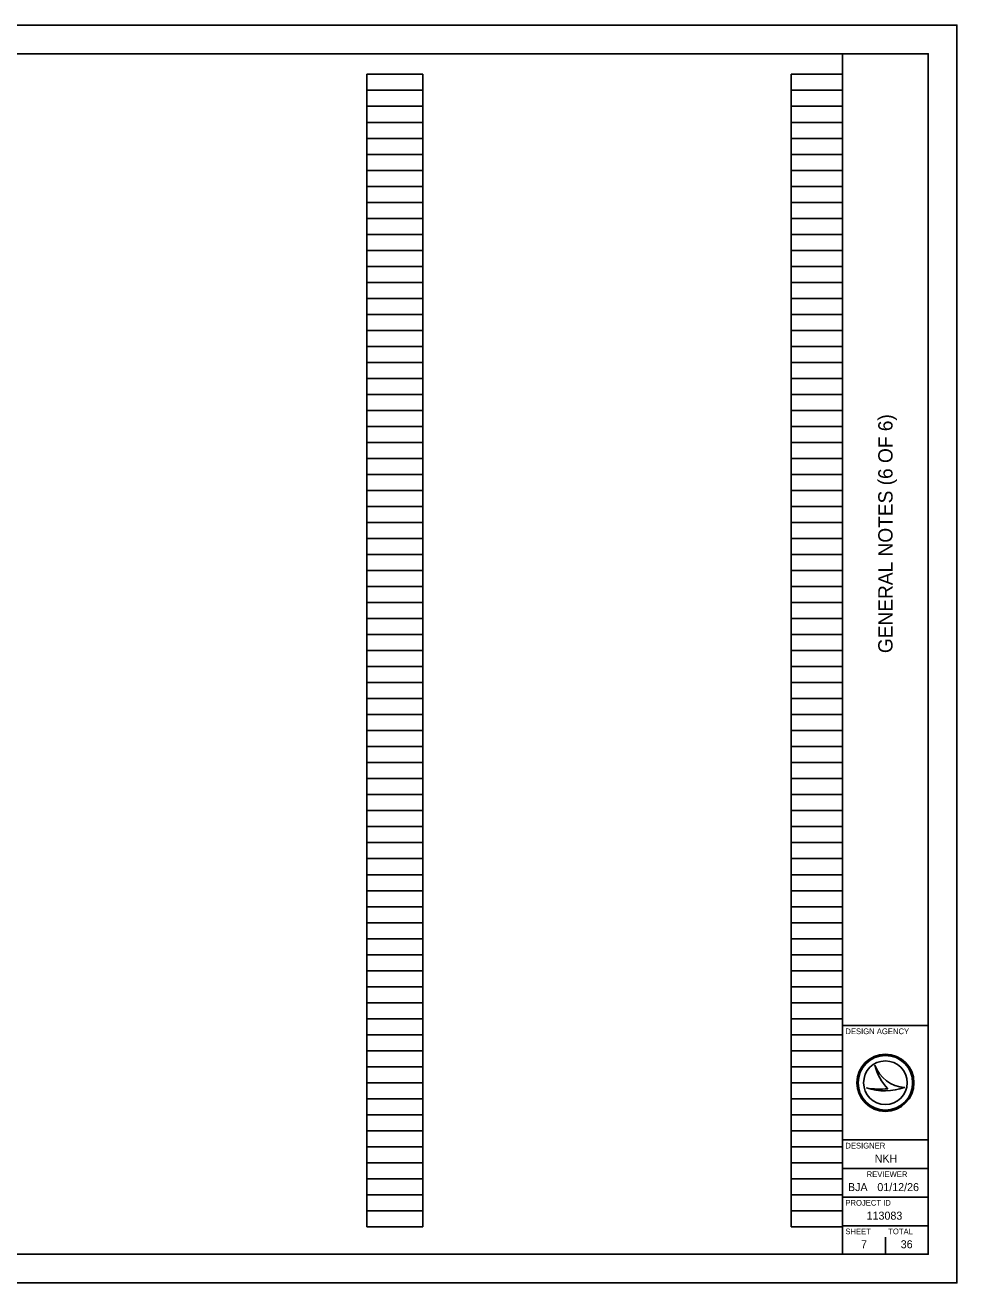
# Model space of a CAD drawing. Extents: x -26.8 to 34, y 0 to 22.
# Drawn here: x 17.7 to 34, y 0 to 22 of the extents above; entities that cross this region are included whole.
import ezdxf

# ---------------------------------------------------------------- set-up
doc = ezdxf.new("R2010")
doc.units = 0
for name, color, linetype in [('SH_Border', 7, 'Continuous'), ('SH_Cut_Line', 7, 'Continuous'), ('SH_Data', 7, 'Continuous')]:
    doc.layers.add(name, color=color, linetype=linetype)

msp = doc.modelspace()

# ---------------------------------------------------------------- linework, layer by layer
at = {"layer": 'SH_Border'}
for p, q in [((32, 0.5), (32, 21.5)), ((32, 4.5), (33.5, 4.5)), ((32, 2.5), (33.5, 2.5)), ((32, 2), (33.5, 2)), ((32, 1.5), (33.5, 1.5)), ((32, 1), (33.5, 1))]:
    msp.add_line(p, q, dxfattribs=at)
msp.add_lwpolyline([(1.5, 21.5), (33.5, 21.5), (33.5, 0.5), (1.5, 0.5)], close=True, dxfattribs=at)
at = {"layer": 'SH_Cut_Line'}
msp.add_lwpolyline([(0, 0), (34, 0), (34, 22), (0, 22)], close=True, dxfattribs=at)
at = {"layer": 'SH_Data'}
for p, q in [((23.68, 0.98), (23.68, 21.14)), ((23.68, 21.14), (24.66, 21.14)), ((24.66, 0.98), (24.66, 21.14)), ((31.1, 0.98), (31.1, 21.14)), ((31.1, 21.14), (32, 21.14)), ((32, 0.98), (32, 21.14)), ((23.68, 20.86), (24.66, 20.86)), ((31.1, 20.86), (32, 20.86)), ((23.68, 20.58), (24.66, 20.58)), ((31.1, 20.58), (32, 20.58)), ((23.68, 20.3), (24.66, 20.3)), ((31.1, 20.3), (32, 20.3)), ((23.68, 20.02), (24.66, 20.02)), ((31.1, 20.02), (32, 20.02)), ((23.68, 19.74), (24.66, 19.74)), ((31.1, 19.74), (32, 19.74)), ((23.68, 19.46), (24.66, 19.46)), ((31.1, 19.46), (32, 19.46)), ((23.68, 19.18), (24.66, 19.18)), ((31.1, 19.18), (32, 19.18)), ((23.68, 18.9), (24.66, 18.9)), ((31.1, 18.9), (32, 18.9)), ((23.68, 18.62), (24.66, 18.62)), ((31.1, 18.62), (32, 18.62)), ((23.68, 18.34), (24.66, 18.34)), ((31.1, 18.34), (32, 18.34)), ((23.68, 18.06), (24.66, 18.06)), ((31.1, 18.06), (32, 18.06)), ((23.68, 17.78), (24.66, 17.78)), ((31.1, 17.78), (32, 17.78)), ((23.68, 17.5), (24.66, 17.5)), ((31.1, 17.5), (32, 17.5)), ((23.68, 17.22), (24.66, 17.22)), ((31.1, 17.22), (32, 17.22)), ((23.68, 16.94), (24.66, 16.94)), ((31.1, 16.94), (32, 16.94)), ((23.68, 16.66), (24.66, 16.66)), ((31.1, 16.66), (32, 16.66)), ((23.68, 16.38), (24.66, 16.38)), ((31.1, 16.38), (32, 16.38)), ((23.68, 16.1), (24.66, 16.1)), ((31.1, 16.1), (32, 16.1)), ((23.68, 15.82), (24.66, 15.82)), ((31.1, 15.82), (32, 15.82)), ((23.68, 15.54), (24.66, 15.54)), ((31.1, 15.54), (32, 15.54)), ((23.68, 15.26), (24.66, 15.26)), ((31.1, 15.26), (32, 15.26)), ((23.68, 14.98), (24.66, 14.98)), ((31.1, 14.98), (32, 14.98)), ((23.68, 14.7), (24.66, 14.7)), ((31.1, 14.7), (32, 14.7)), ((23.68, 14.42), (24.66, 14.42)), ((31.1, 14.42), (32, 14.42)), ((23.68, 14.14), (24.66, 14.14)), ((31.1, 14.14), (32, 14.14)), ((23.68, 13.86), (24.66, 13.86)), ((31.1, 13.86), (32, 13.86)), ((23.68, 13.58), (24.66, 13.58)), ((31.1, 13.58), (32, 13.58)), ((23.68, 13.3), (24.66, 13.3)), ((31.1, 13.3), (32, 13.3)), ((23.68, 13.02), (24.66, 13.02)), ((31.1, 13.02), (32, 13.02)), ((23.68, 12.74), (24.66, 12.74)), ((31.1, 12.74), (32, 12.74)), ((23.68, 12.46), (24.66, 12.46)), ((31.1, 12.46), (32, 12.46)), ((23.68, 12.18), (24.66, 12.18)), ((31.1, 12.18), (32, 12.18)), ((23.68, 11.9), (24.66, 11.9)), ((31.1, 11.9), (32, 11.9)), ((23.68, 11.62), (24.66, 11.62)), ((31.1, 11.62), (32, 11.62)), ((23.68, 11.34), (24.66, 11.34)), ((31.1, 11.34), (32, 11.34)), ((23.68, 11.06), (24.66, 11.06)), ((31.1, 11.06), (32, 11.06)), ((23.68, 10.78), (24.66, 10.78)), ((31.1, 10.78), (32, 10.78)), ((23.68, 10.5), (24.66, 10.5)), ((31.1, 10.5), (32, 10.5)), ((23.68, 10.22), (24.66, 10.22)), ((31.1, 10.22), (32, 10.22)), ((23.68, 9.94), (24.66, 9.94)), ((31.1, 9.94), (32, 9.94)), ((23.68, 9.66), (24.66, 9.66)), ((31.1, 9.66), (32, 9.66)), ((23.68, 9.38), (24.66, 9.38)), ((31.1, 9.38), (32, 9.38)), ((23.68, 9.1), (24.66, 9.1)), ((31.1, 9.1), (32, 9.1)), ((23.68, 8.82), (24.66, 8.82)), ((31.1, 8.82), (32, 8.82)), ((23.68, 8.54), (24.66, 8.54)), ((31.1, 8.54), (32, 8.54)), ((23.68, 8.26), (24.66, 8.26)), ((31.1, 8.26), (32, 8.26)), ((23.68, 7.98), (24.66, 7.98)), ((31.1, 7.98), (32, 7.98)), ((23.68, 7.7), (24.66, 7.7)), ((31.1, 7.7), (32, 7.7)), ((23.68, 7.42), (24.66, 7.42)), ((31.1, 7.42), (32, 7.42)), ((23.68, 7.14), (24.66, 7.14)), ((31.1, 7.14), (32, 7.14)), ((23.68, 6.86), (24.66, 6.86)), ((31.1, 6.86), (32, 6.86)), ((23.68, 6.58), (24.66, 6.58)), ((31.1, 6.58), (32, 6.58)), ((23.68, 6.3), (24.66, 6.3)), ((31.1, 6.3), (32, 6.3)), ((23.68, 6.02), (24.66, 6.02)), ((31.1, 6.02), (32, 6.02)), ((23.68, 5.74), (24.66, 5.74)), ((31.1, 5.74), (32, 5.74)), ((23.68, 5.46), (24.66, 5.46)), ((31.1, 5.46), (32, 5.46)), ((23.68, 5.18), (24.66, 5.18)), ((31.1, 5.18), (32, 5.18)), ((23.68, 4.9), (24.66, 4.9)), ((31.1, 4.9), (32, 4.9)), ((23.68, 4.62), (24.66, 4.62)), ((31.1, 4.62), (32, 4.62)), ((23.68, 4.34), (24.66, 4.34)), ((31.1, 4.34), (32, 4.34)), ((23.68, 4.06), (24.66, 4.06)), ((31.1, 4.06), (32, 4.06)), ((23.68, 3.78), (24.66, 3.78)), ((31.1, 3.78), (32, 3.78)), ((32.567, 3.81), (32.567, 3.81)), ((23.68, 3.5), (24.66, 3.5)), ((31.1, 3.5), (32, 3.5)), ((32.417, 3.41), (32.417, 3.41)), ((32.75, 3.5), (32.75, 3.5)), ((33.087, 3.419), (33.087, 3.419)), ((23.68, 3.22), (24.66, 3.22)), ((31.1, 3.22), (32, 3.22)), ((23.68, 2.94), (24.66, 2.94)), ((31.1, 2.94), (32, 2.94)), ((23.68, 2.66), (24.66, 2.66)), ((31.1, 2.66), (32, 2.66)), ((23.68, 2.38), (24.66, 2.38)), ((31.1, 2.38), (32, 2.38)), ((23.68, 2.1), (24.66, 2.1)), ((31.1, 2.1), (32, 2.1)), ((23.68, 1.82), (24.66, 1.82)), ((31.1, 1.82), (32, 1.82)), ((23.68, 1.54), (24.66, 1.54)), ((31.1, 1.54), (32, 1.54)), ((23.68, 1.26), (24.66, 1.26)), ((31.1, 1.26), (32, 1.26)), ((23.68, 0.98), (24.66, 0.98)), ((31.1, 0.98), (32, 0.98)), ((32.375, 0.675), (32.375, 0.675)), ((32.75, 0.5), (32.75, 0.8))]:
    msp.add_line(p, q, dxfattribs=at)
for radius in [0.5, 0.477, 0.477, 0.382]:
    msp.add_circle((32.75, 3.5), radius, dxfattribs=at)
for centre, radius, start, end in [((33.116, 3.998), 0.58, 198.9257, 198.9319), ((33.347, 3.97), 0.796, 191.6379, 191.6421), ((33.116, 3.998), 0.58, 198.9319, 267.1657), ((33.347, 3.97), 0.796, 191.6421, 226.0947), ((32.739, 4.37), 1.013, 251.4576, 290.0832), ((32.648, 4.654), 1.266, 259.4964, 259.4995), ((32.739, 4.37), 1.013, 251.4527, 251.4576), ((32.648, 4.654), 1.266, 259.4995, 276.6672)]:
    msp.add_arc(centre, radius, start, end, dxfattribs=at)

# ---------------------------------------------------------------- texts
msp.add_text('GENERAL NOTES (6 OF 6)', height=0.25, rotation=90, dxfattribs=at).set_placement((32.875, 11.015))
for s, height, p in [('DESIGN AGENCY', 0.1, (32.05, 4.35)), ('DESIGNER', 0.1, (32.05, 2.35)), ('NKH', 0.14, (32.562, 2.105)), ('REVIEWER', 0.1, (32.422, 1.85)), ('BJA', 0.14, (32.095, 1.605)), ('01/12/26', 0.14, (32.609, 1.605)), ('PROJECT ID', 0.1, (32.05, 1.35)), ('113083', 0.14, (32.421, 1.105)), ('SHEET', 0.1, (32.05, 0.85)), ('TOTAL', 0.1, (32.8, 0.85)), ('7', 0.14, (32.324, 0.605)), ('36', 0.14, (33.018, 0.605))]:
    msp.add_text(s, height=height, dxfattribs=at).set_placement(p)

doc.saveas('drawing.dxf')
